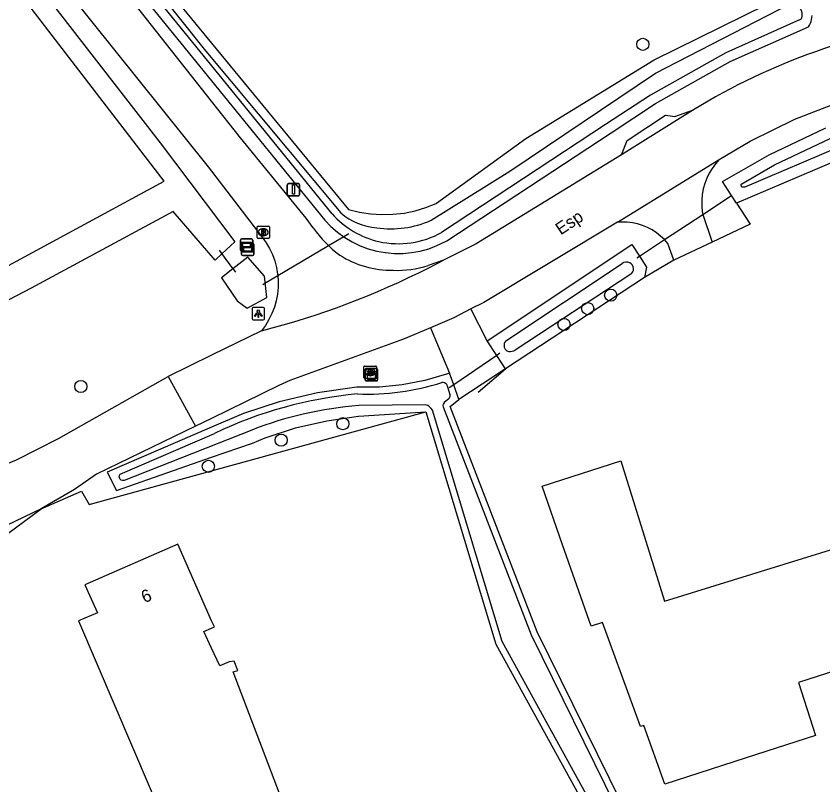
# Model space of a CAD drawing. Extents: x 161389 to 162585, y 388479 to 389761.
# Drawn here: x 162484.3 to 162549.2, y 389564.4 to 389626.2 of the extents above; entities that cross this region are included whole.
import ezdxf

# ---------------------------------------------------------------- set-up
doc = ezdxf.new("R2010")
doc.units = 0
for name, color, linetype in [('IMGEO_Boom', 7, 'Continuous'), ('IMGEO_Bouwland', 7, 'Continuous'), ('IMGEO_Brandkraan', 7, 'Continuous'), ('IMGEO_Duiker', 7, 'Continuous'), ('IMGEO_Erf', 7, 'Continuous'), ('IMGEO_Groenvoorziening', 7, 'Continuous'), ('IMGEO_Hek', 7, 'Continuous'), ('IMGEO_Kast', 7, 'Continuous'), ('IMGEO_Lichtpunt', 7, 'Continuous'), ('IMGEO_Openbare_ruimte_label', 7, 'Continuous'), ('IMGEO_Pand', 7, 'Continuous'), ('IMGEO_Pand_nummerreeks', 7, 'Continuous'), ('IMGEO_Rijbaan_lokaal_gesloten', 7, 'Continuous'), ('IMGEO_Rijbaan_lokaal_open', 7, 'Continuous'), ('IMGEO_Rioolput', 7, 'Continuous'), ('IMGEO_Verkeersbordpaal', 7, 'Continuous'), ('IMGEO_Verklikker', 7, 'Continuous'), ('IMGEO_Voetpad_open', 7, 'Continuous'), ('IMGEO_Waterloop', 7, 'Continuous')]:
    doc.layers.add(name, color=color, linetype=linetype)

msp = doc.modelspace()

# ---------------------------------------------------------------- linework, layer by layer
at = {"layer": 'IMGEO_Boom'}
for centre in [(162534.679, 389623.918), (162532.091, 389603.754), (162530.243, 389602.666), (162528.339, 389601.388), (162489.483, 389596.41), (162510.55, 389593.41), (162505.592, 389592.083), (162499.737, 389589.986)]:
    msp.add_circle(centre, 0.489, dxfattribs=at)
at = {"layer": 'IMGEO_Bouwland'}
msp.add_lwpolyline([(162444.281, 389695.626), (162444.976, 389694.347), (162446.876, 389691.104), (162455.38, 389679.171), (162459.144, 389674.721), (162460.547, 389672.643), (162488.264, 389637.946), (162489.578, 389636.693), (162500, 389624.024), (162511.007, 389610.643), (162511.882, 389610.425), (162512.773, 389610.287), (162513.673, 389610.228), (162514.574, 389610.25), (162515.47, 389610.353), (162516.353, 389610.535), (162517.216, 389610.795), (162518.053, 389611.132), (162518.071, 389611.14), (162525.26, 389616.35), (162535.579, 389622.671), (162546.422, 389628.045)], dxfattribs=at)
at = {"layer": 'IMGEO_Brandkraan'}
for p, q in [((162503.653, 389608.378), (162503.653, 389609.23)), ((162503.728, 389609.304), (162504.58, 389609.304)), ((162504.141, 389609.084), (162504.166, 389609.084)), ((162504.654, 389609.23), (162504.654, 389608.378)), ((162504.164, 389608.524), (162504.139, 389608.524)), ((162504.58, 389608.304), (162503.728, 389608.304))]:
    msp.add_line(p, q, dxfattribs=at)
for points in [[(162503.653, 389608.378), (162503.653, 389609.23)], [(162503.728, 389609.304), (162504.58, 389609.304)], [(162504.001, 389609.004), (162504.001, 389608.604), (162504.214, 389608.604)], [(162504.232, 389609.004), (162504.001, 389609.004)], [(162504.654, 389609.23), (162504.654, 389608.378)], [(162504.18, 389608.923), (162504.126, 389608.923), (162504.126, 389608.847)], [(162504.126, 389608.847), (162504.179, 389608.847)], [(162504.188, 389608.771), (162504.126, 389608.771), (162504.126, 389608.69)], [(162504.126, 389608.69), (162504.188, 389608.69)], [(162504.58, 389608.304), (162503.728, 389608.304)]]:
    msp.add_lwpolyline(points, dxfattribs=at)
for centre, radius, start, end in [((162503.73, 389609.228), 0.0765, 91.55205, 178.44795), ((162503.73, 389609.228), 0.0765, 91.55205, 178.44795), ((162504.236, 389608.859), 0.145, 59.4692, 91.53667), ((162504.261, 389608.906), 0.0922, 285.51372, 58.15012), ((162504.578, 389609.228), 0.0765, 1.55205, 88.44795), ((162504.578, 389609.228), 0.0765, 1.55205, 88.44795), ((162503.73, 389608.38), 0.0765, 181.55205, 268.44795), ((162503.73, 389608.38), 0.0765, 181.55205, 268.44795), ((162504.181, 389608.885), 0.0379, 267.82845, 90.93552), ((162504.189, 389608.73), 0.0404, 269.87594, 90.50774), ((162504.22, 389608.855), 0.251, 268.66757, 293.53466), ((162504.266, 389608.714), 0.105, 301.31148, 78.98903), ((162504.578, 389608.38), 0.0765, 271.55205, 358.44795), ((162504.578, 389608.38), 0.0765, 271.55205, 358.44795)]:
    msp.add_arc(centre, radius, start, end, dxfattribs=at)
for centre, major_axis, ratio, start_param, end_param in [((162504.14, 389608.804), (-0.387, 0.002), 0.722429, 4.712389, 7.853982), ((162504.165, 389608.804), (-0.39, 0.002), 0.717154, 1.570796, 4.712389)]:
    msp.add_ellipse(centre, major_axis=major_axis, ratio=ratio, start_param=start_param, end_param=end_param, dxfattribs=at)
at = {"layer": 'IMGEO_Duiker'}
for points in [[(162534.192, 389606.753), (162534.396, 389606.887), (162536.419, 389608.216), (162539.494, 389610.236), (162541.814, 389611.76)], [(162511.026, 389608.69), (162510.617, 389608.447), (162509.979, 389608.067), (162505.315, 389605.29), (162504.421, 389604.757), (162504.116, 389604.576)], [(162500.595, 389607.36), (162501.146, 389606.618), (162501.201, 389606.543), (162501.223, 389606.514), (162501.485, 389606.161), (162501.499, 389606.143), (162501.554, 389606.068), (162501.647, 389605.943), (162501.907, 389605.593)], [(162523.177, 389599.072), (162522.929, 389598.903), (162519.465, 389596.546), (162519.088, 389596.289)]]:
    msp.add_lwpolyline(points, dxfattribs=at)
at = {"layer": 'IMGEO_Erf'}
for points in [[(162556.26, 389616.875), (162551.015, 389614.89), (162542.21, 389611.153)], [(162534.818, 389605.175), (162523.628, 389597.829)], [(162541.072, 389550.047), (162538.326, 389554.399), (162532.952, 389562.914), (162526.187, 389576.665), (162519.175, 389594.805), (162519.885, 389595.351)], [(162517.235, 389594.37), (162522.858, 389575.675), (162530.551, 389561.722), (162536.666, 389552.847), (162539.23, 389549.09), (162539.513, 389548.715), (162540.796, 389547.168)]]:
    msp.add_lwpolyline(points, dxfattribs=at)
at = {"layer": 'IMGEO_Groenvoorziening'}
for points in [[(162488.254, 389635.427), (162500, 389620.974), (162509.104, 389609.771), (162509.593, 389609.263), (162510.125, 389608.801), (162510.617, 389608.447), (162510.697, 389608.389), (162511.302, 389608.029), (162511.938, 389607.725), (162512.598, 389607.479), (162513.278, 389607.292), (162513.972, 389607.167), (162514.674, 389607.105), (162515.379, 389607.106), (162516.08, 389607.169), (162516.774, 389607.295), (162517.453, 389607.483), (162518.113, 389607.73), (162518.748, 389608.035), (162518.902, 389608.12), (162532.116, 389616.803), (162535.697, 389619.162), (162541.71, 389622.525), (162548, 389625.337), (162548.079, 389625.472), (162548.146, 389625.614), (162548.2, 389625.762), (162548.24, 389625.913), (162548.267, 389626.068), (162548.28, 389626.224)], [(162532.951, 389615.044), (162533.406, 389616.19), (162536.498, 389618.212), (162537.25, 389618.115), (162538.761, 389618.657)], [(162542.21, 389611.153), (162541.814, 389611.76), (162541.087, 389612.876), (162544.825, 389615.043), (162549.393, 389617.208)], [(162542.21, 389611.153), (162543.318, 389609.455), (162540.263, 389608.011)], [(162522.166, 389600.076), (162533.794, 389607.812), (162534.396, 389606.887), (162534.974, 389605.997), (162534.818, 389605.175)], [(162537.178, 389606.553), (162534.818, 389605.175)], [(162519.138, 389597.477), (162518.891, 389597.393), (162517.131, 389596.889), (162515.332, 389596.545), (162513.51, 389596.363), (162511.679, 389596.344), (162508.524, 389595.901), (162505.421, 389595.177), (162502.557, 389594.24), (162500, 389593.133), (162491.61, 389589.502), (162492.351, 389588.053), (162500, 389590.716), (162503.274, 389591.856), (162504.295, 389592.265), (162506.749, 389593.071), (162509.264, 389593.654), (162511.822, 389594.01), (162517.235, 389594.37)], [(162486.294, 389586.559), (162489.546, 389587.986), (162490.14, 389586.904), (162517.235, 389594.37)], [(162469.453, 389581.059), (162480.039, 389582.45), (162482.871, 389584.036), (162486.294, 389586.559)]]:
    msp.add_lwpolyline(points, dxfattribs=at)
at = {"layer": 'IMGEO_Hek'}
msp.add_lwpolyline([(162521.445, 389595.94), (162523.628, 389597.829)], dxfattribs=at)
at = {"layer": 'IMGEO_Kast'}
for p, q in [((162512.344, 389596.928), (162512.344, 389597.769)), ((162512.344, 389597.769), (162512.344, 389596.928)), ((162512.419, 389597.853), (162513.26, 389597.853)), ((162513.26, 389597.853), (162512.419, 389597.853)), ((162513.344, 389597.778), (162513.344, 389596.937)), ((162513.344, 389596.937), (162513.344, 389597.778)), ((162513.269, 389596.853), (162512.428, 389596.853)), ((162512.428, 389596.853), (162513.269, 389596.853))]:
    msp.add_line(p, q, dxfattribs=at)
for points in [[(162512.539, 389597.643), (162513.139, 389597.643), (162513.139, 389597.558), (162512.539, 389597.558), (162512.539, 389597.643)], [(162512.539, 389597.468), (162513.139, 389597.468), (162513.139, 389596.979), (162512.539, 389596.979), (162512.539, 389597.468)]]:
    msp.add_lwpolyline(points, dxfattribs=at)
msp.add_circle((162512.623, 389597.317), 0.0377, dxfattribs=at)
for centre, start, end in [((162512.422, 389597.775), 92.4484, 184.28452), ((162512.422, 389597.775), 92.4484, 184.28452), ((162513.266, 389597.775), 2.4484, 94.28452), ((162513.266, 389597.775), 2.4484, 94.28452), ((162512.422, 389596.931), 182.4484, 274.28452), ((162512.422, 389596.931), 182.4484, 274.28452), ((162513.266, 389596.931), 272.4484, 4.28452), ((162513.266, 389596.931), 272.4484, 4.28452)]:
    msp.add_arc(centre, 0.0779, start, end, dxfattribs=at)
at = {"layer": 'IMGEO_Lichtpunt'}
for p, q in [((162503.253, 389602.663), (162503.253, 389601.856)), ((162503.253, 389602.663), (162503.253, 389601.856)), ((162504.155, 389602.758), (162503.347, 389602.758)), ((162504.155, 389602.758), (162503.347, 389602.758)), ((162504.249, 389601.856), (162504.249, 389602.663)), ((162504.249, 389601.856), (162504.249, 389602.663)), ((162503.347, 389601.762), (162504.155, 389601.762)), ((162503.347, 389601.762), (162504.155, 389601.762))]:
    msp.add_line(p, q, dxfattribs=at)
for points in [[(162503.627, 389602.327), (162503.666, 389602.299), (162503.478, 389602.037), (162503.44, 389602.064), (162503.627, 389602.327)], [(162503.729, 389602.279), (162503.776, 389602.279), (162503.776, 389601.957), (162503.729, 389601.957), (162503.729, 389602.279)], [(162503.839, 389602.299), (162503.877, 389602.326), (162504.064, 389602.064), (162504.025, 389602.036), (162503.839, 389602.299)]]:
    msp.add_lwpolyline(points, dxfattribs=at)
msp.add_circle((162503.752, 389602.461), 0.0994, dxfattribs=at)
for centre, start, end in [((162503.347, 389602.663), 90, 180), ((162503.347, 389602.663), 90, 180), ((162504.155, 389602.663), 0, 90), ((162504.155, 389602.663), 0, 90), ((162503.347, 389601.856), 180, 270), ((162503.347, 389601.856), 180, 270), ((162504.155, 389601.856), 270, 0), ((162504.155, 389601.856), 270, 360)]:
    msp.add_arc(centre, 0.0946, start, end, dxfattribs=at)
at = {"layer": 'IMGEO_Pand'}
for points in [[(162565.517, 389578.496), (162547.191, 389572.588), (162548.561, 389568.331), (162543.802, 389566.8), (162536.446, 389564.434), (162534.742, 389569.151), (162534.484, 389569.057), (162531.437, 389577.419), (162530.514, 389577.136), (162528.223, 389583.678), (162526.571, 389588.397), (162532.896, 389590.432), (162536.408, 389579.136), (162562.687, 389587.272), (162565.517, 389578.496)], [(162499.328, 389554.103), (162500, 389554.371), (162507.803, 389557.479), (162501.735, 389573.462), (162502.112, 389573.572), (162501.817, 389574.322), (162501.417, 389574.255), (162500.655, 389573.945), (162500, 389575.362), (162499.378, 389576.707), (162500, 389576.982), (162500.217, 389577.078), (162500, 389577.568), (162497.277, 389583.713), (162489.806, 389580.447), (162490.812, 389578.214), (162489.287, 389577.554), (162499.328, 389554.103)]]:
    msp.add_lwpolyline(points, dxfattribs=at)
at = {"layer": 'IMGEO_Rijbaan_lokaal_gesloten'}
for points in [[(162508.175, 389609.158), (162507.599, 389609.947), (162502.332, 389616.392), (162500, 389619.349), (162487.536, 389635.155), (162471.962, 389655.135), (162460.381, 389668.927)], [(162457.368, 389666.342), (162468.15, 389652.663), (162484.593, 389632.945), (162499.723, 389614.076), (162500, 389613.714), (162504.042, 389608.438), (162504.066, 389608.408), (162504.38, 389607.967), (162504.653, 389607.499), (162504.884, 389607.009), (162505.07, 389606.5), (162505.209, 389605.977), (162505.302, 389605.443), (162505.315, 389605.29), (162505.346, 389604.904), (162505.342, 389604.362), (162505.289, 389603.823), (162505.189, 389603.291), (162505.041, 389602.77), (162504.848, 389602.264), (162504.61, 389601.778), (162504.33, 389601.314), (162504.009, 389600.878)], [(162518.658, 389606.555), (162517.4, 389606.137)], [(162517.458, 389605.949), (162518.658, 389606.555)], [(162409.988, 389580.122), (162414.314, 389582.066), (162419.315, 389583.822), (162424.453, 389585.125), (162429.686, 389585.963), (162434.974, 389586.33), (162436.417, 389586.413), (162439.61, 389586.598), (162464.371, 389586.252), (162468.477, 389586.379), (162472.556, 389586.873), (162476.574, 389587.729), (162480.499, 389588.94), (162484.301, 389590.498), (162487.678, 389592.234), (162496.502, 389597.202)], [(162496.502, 389597.202), (162498.712, 389593.205)], [(162498.712, 389593.205), (162490.738, 389589.364), (162488.966, 389588.132), (162486.294, 389586.559)], [(162486.294, 389586.559), (162483.492, 389585.232), (162480.582, 389584.16), (162477.589, 389583.352), (162474.535, 389582.815), (162466.407, 389582.224), (162437.665, 389582.372), (162436.345, 389582.328), (162428.651, 389581.666), (162425.623, 389581.213), (162425.125, 389580.99)]]:
    msp.add_lwpolyline(points, dxfattribs=at)
for centre, radius, start, end in [((162515.884, 389614.512), 9.386, 214.78193, 233.49202), ((162514.493, 389613.551), 7.805, 237.50831, 270.7595), ((162487.359, 389665.406), 66.642, 284.46834, 296.84997), ((162514.92, 389613.691), 7.95, 267.66256, 288.17404)]:
    msp.add_arc(centre, radius, start, end, dxfattribs=at)
at = {"layer": 'IMGEO_Rijbaan_lokaal_open'}
for points in [[(162540.808, 389614.65), (162543.297, 389616.119), (162546.908, 389617.892), (162550.663, 389619.336), (162554.532, 389620.438), (162557.552, 389621.024), (162561.524, 389621.473), (162562.854, 389621.493)], [(162538.761, 389618.657), (162532.951, 389615.044)], [(162532.951, 389615.044), (162521.27, 389607.875), (162518.658, 389606.555)], [(162532.625, 389609.608), (162540.808, 389614.65)], [(162540.808, 389614.65), (162540.511, 389614.309), (162540.245, 389613.942), (162540.013, 389613.553), (162539.817, 389613.146), (162539.658, 389612.722), (162539.537, 389612.285), (162539.456, 389611.84), (162539.415, 389611.389), (162539.414, 389610.936), (162539.454, 389610.485), (162539.494, 389610.236), (162540.263, 389608.011)], [(162532.625, 389609.608), (162521.889, 389603.165), (162520.856, 389602.637)], [(162537.178, 389606.553), (162536.693, 389607.913), (162536.419, 389608.216), (162536.108, 389608.504), (162535.774, 389608.763), (162535.417, 389608.991), (162535.041, 389609.186), (162534.649, 389609.347), (162534.245, 389609.473), (162533.831, 389609.561), (162533.41, 389609.613), (162532.987, 389609.626), (162532.625, 389609.608)], [(162540.263, 389608.011), (162537.178, 389606.553)], [(162520.856, 389602.637), (162519.486, 389601.936), (162517.589, 389601.132)], [(162504.009, 389600.878), (162500, 389598.915), (162496.502, 389597.202)], [(162517.589, 389601.132), (162515.441, 389600.222), (162506.297, 389596.882), (162505.406, 389596.487), (162500, 389593.836), (162498.712, 389593.205)]]:
    msp.add_lwpolyline(points, dxfattribs=at)
msp.add_arc((162565.779, 389574.575), 51.702, 97.41083, 121.50429, dxfattribs=at)
at = {"layer": 'IMGEO_Rioolput'}
for p, q in [((162512.251, 389597.124), (162512.251, 389597.976)), ((162512.326, 389598.05), (162513.178, 389598.05)), ((162513.252, 389597.976), (162513.252, 389597.124)), ((162512.739, 389597.83), (162512.764, 389597.83)), ((162513.178, 389597.05), (162512.326, 389597.05)), ((162512.762, 389597.27), (162512.737, 389597.27))]:
    msp.add_line(p, q, dxfattribs=at)
for points in [[(162512.251, 389597.124), (162512.251, 389597.976)], [(162512.326, 389598.05), (162513.178, 389598.05)], [(162513.252, 389597.976), (162513.252, 389597.124)], [(162512.84, 389597.748), (162512.588, 389597.75), (162512.588, 389597.35)], [(162512.588, 389597.35), (162512.712, 389597.35), (162512.712, 389597.512), (162512.723, 389597.512)], [(162512.766, 389597.669), (162512.712, 389597.669), (162512.712, 389597.588)], [(162512.712, 389597.588), (162512.764, 389597.588)], [(162512.77, 389597.483), (162512.841, 389597.35), (162512.981, 389597.35), (162512.916, 389597.476)], [(162513.178, 389597.05), (162512.326, 389597.05)]]:
    msp.add_lwpolyline(points, dxfattribs=at)
for centre, radius, start, end in [((162512.328, 389597.974), 0.0765, 91.55205, 178.44795), ((162512.328, 389597.974), 0.0765, 91.55205, 178.44795), ((162513.176, 389597.974), 0.0765, 1.55205, 88.44795), ((162513.176, 389597.974), 0.0765, 1.55205, 88.44795), ((162512.722, 389597.459), 0.0533, 26.02933, 88.69889), ((162512.748, 389597.777), 0.19, 274.7715, 282.96867), ((162512.772, 389597.573), 0.0964, 77.00612, 93.18647), ((162512.786, 389597.63), 0.0378, 276.66336, 79.67722), ((162512.839, 389597.638), 0.109, 350.36119, 89.41601), ((162512.837, 389597.638), 0.112, 277.58423, 350.98172), ((162512.821, 389597.423), 0.108, 29.51342, 73.79051), ((162512.328, 389597.126), 0.0765, 181.55205, 268.44795), ((162512.328, 389597.126), 0.0765, 181.55205, 268.44795), ((162513.176, 389597.126), 0.0765, 271.55205, 358.44795), ((162513.176, 389597.126), 0.0765, 271.55205, 358.44795)]:
    msp.add_arc(centre, radius, start, end, dxfattribs=at)
for centre, major_axis, ratio, start_param, end_param in [((162512.738, 389597.55), (-0.387, 0.002), 0.722429, 4.712389, 7.853982), ((162512.763, 389597.55), (-0.39, 0.002), 0.717154, 1.570796, 4.712389)]:
    msp.add_ellipse(centre, major_axis=major_axis, ratio=ratio, start_param=start_param, end_param=end_param, dxfattribs=at)
at = {"layer": 'IMGEO_Verkeersbordpaal'}
for p, q in [((162506.086, 389611.833), (162506.086, 389612.633)), ((162506.086, 389612.633), (162506.086, 389611.833)), ((162506.186, 389612.733), (162506.976, 389612.733)), ((162506.976, 389612.733), (162506.186, 389612.733)), ((162507.076, 389612.633), (162507.076, 389611.833)), ((162507.076, 389611.833), (162507.076, 389612.633)), ((162506.976, 389611.733), (162506.186, 389611.733)), ((162506.186, 389611.733), (162506.976, 389611.733))]:
    msp.add_line(p, q, dxfattribs=at)
msp.add_lwpolyline([(162506.506, 389612.608), (162506.656, 389612.608), (162506.656, 389611.858), (162506.506, 389611.858), (162506.506, 389612.608)], dxfattribs=at)
for centre, start, end in [((162506.186, 389612.633), 90, 180), ((162506.186, 389612.633), 90, 180), ((162506.976, 389612.633), 0, 90), ((162506.976, 389612.633), 360, 90), ((162506.186, 389611.833), 180, 270), ((162506.186, 389611.833), 180, 270), ((162506.976, 389611.833), 270, 0), ((162506.976, 389611.833), 270, 0)]:
    msp.add_arc(centre, 0.1, start, end, dxfattribs=at)
at = {"layer": 'IMGEO_Verklikker'}
for p, q in [((162502.309, 389607.376), (162502.309, 389608.176)), ((162502.309, 389608.176), (162502.309, 389607.376)), ((162502.401, 389607.024), (162502.401, 389607.824)), ((162502.401, 389607.824), (162502.401, 389607.024)), ((162502.409, 389608.276), (162503.199, 389608.276)), ((162503.199, 389608.276), (162502.409, 389608.276)), ((162502.501, 389607.924), (162503.291, 389607.924)), ((162503.291, 389607.924), (162502.501, 389607.924)), ((162503.299, 389608.176), (162503.299, 389607.376)), ((162503.299, 389607.376), (162503.299, 389608.176)), ((162503.391, 389607.824), (162503.391, 389607.024)), ((162503.391, 389607.024), (162503.391, 389607.824)), ((162503.199, 389607.276), (162502.409, 389607.276)), ((162502.409, 389607.276), (162503.199, 389607.276)), ((162503.291, 389606.924), (162502.501, 389606.924)), ((162502.501, 389606.924), (162503.291, 389606.924))]:
    msp.add_line(p, q, dxfattribs=at)
for points in [[(162502.41, 389608.008), (162503.198, 389608.008), (162503.198, 389607.544), (162502.41, 389607.544), (162502.41, 389608.008)], [(162502.475, 389607.943), (162502.475, 389607.609), (162503.133, 389607.609), (162503.133, 389607.943), (162502.475, 389607.943)], [(162502.502, 389607.656), (162503.29, 389607.656), (162503.29, 389607.192), (162502.502, 389607.192), (162502.502, 389607.656)], [(162502.567, 389607.591), (162502.567, 389607.257), (162503.225, 389607.257), (162503.225, 389607.591), (162502.567, 389607.591)]]:
    msp.add_lwpolyline(points, dxfattribs=at)
for centre, start, end in [((162502.409, 389608.176), 90, 180), ((162502.409, 389608.176), 90, 180), ((162502.501, 389607.824), 90, 180), ((162502.501, 389607.824), 90, 180), ((162503.199, 389608.176), 0, 90), ((162503.199, 389608.176), 360, 90), ((162503.291, 389607.824), 0, 90), ((162503.291, 389607.824), 360, 90), ((162502.409, 389607.376), 180, 270), ((162502.409, 389607.376), 180, 270), ((162503.199, 389607.376), 270, 0), ((162503.199, 389607.376), 270, 0), ((162502.501, 389607.024), 180, 270), ((162502.501, 389607.024), 180, 270), ((162503.291, 389607.024), 270, 0), ((162503.291, 389607.024), 270, 0)]:
    msp.add_arc(centre, 0.1, start, end, dxfattribs=at)
at = {"layer": 'IMGEO_Voetpad_open'}
for points in [[(162522.166, 389600.076), (162520.856, 389602.637)], [(162517.589, 389601.132), (162519.138, 389597.477)], [(162523.628, 389597.829), (162522.929, 389598.903), (162522.166, 389600.076)], [(162519.885, 389595.351), (162519.465, 389596.546), (162519.138, 389597.477)], [(162523.628, 389597.829), (162519.885, 389595.351)]]:
    msp.add_lwpolyline(points, dxfattribs=at)
at = {"layer": 'IMGEO_Waterloop'}
for points in [[(162480.118, 389604.237), (162496.188, 389612.908), (162481.084, 389632.533), (162456.218, 389661.773), (162455.163, 389662.824), (162449.463, 389669.131), (162445.046, 389674.921), (162440.477, 389682.073), (162436.565, 389689.605)], [(162459.319, 389673.752), (162499.393, 389623.525), (162510.388, 389610.356)], [(162457.733, 389662.99), (162482.436, 389633.29), (162495.856, 389615.998), (162501.859, 389608.049), (162500.817, 389607.061), (162500.283, 389606.554), (162496.893, 389610.475), (162485.48, 389604.317), (162481.249, 389602.123)], [(162509.693, 389610.292), (162500.61, 389621.47), (162488.867, 389635.919)], [(162517.644, 389609.766), (162523.986, 389613.721), (162535.683, 389621.595), (162546.472, 389627.155)], [(162547.281, 389625.877), (162541.357, 389623.228), (162535.288, 389619.834), (162531.684, 389617.46), (162518.496, 389608.794)], [(162542.564, 389612.602), (162542.645, 389612.71), (162545.256, 389614.223), (162549.752, 389616.354), (162554.44, 389618.082)], [(162556.132, 389617.816), (162550.67, 389615.749), (162542.877, 389612.441)], [(162542.877, 389612.441), (162542.728, 389612.427), (162542.706, 389612.43), (162542.664, 389612.439)], [(162500.799, 389605.13), (162502.062, 389603.302), (162502.856, 389602.704), (162504.443, 389603.561), (162504.244, 389605.272), (162502.899, 389606.807), (162501.71, 389605.858), (162500.799, 389605.13)], [(162523.652, 389600.073), (162533.01, 389606.298)], [(162533.699, 389605.428), (162524.413, 389599.333)], [(162523.636, 389599.37), (162523.531, 389599.597)], [(162518.876, 389596.584), (162518.953, 389596.366), (162519.164, 389595.763)], [(162519.132, 389595.515), (162519.061, 389595.402), (162518.729, 389595.147)], [(162517.207, 389594.936), (162511.831, 389594.872)], [(162518.606, 389594.771), (162525.689, 389576.447), (162532.477, 389562.648), (162537.867, 389554.109), (162540.628, 389549.734), (162543.969, 389545.48), (162547.044, 389540.999), (162549.281, 389536.684), (162551.339, 389531.009), (162553.057, 389526.283)], [(162553.023, 389524.065), (162552.828, 389524.145), (162552.749, 389524.207), (162552.626, 389524.387), (162552.561, 389524.538), (162552.495, 389524.762), (162552.373, 389525.281), (162550.517, 389532.219), (162548.715, 389536.979), (162547.511, 389539.233), (162544.866, 389543.113), (162541.214, 389547.515), (162539.939, 389549.052), (162539.671, 389549.407), (162537.114, 389553.154), (162531.013, 389562.008), (162523.361, 389575.887), (162517.765, 389594.494)], [(162503.226, 389592.903), (162492.953, 389588.838), (162492.831, 389588.849), (162492.721, 389588.876)], [(162492.571, 389589.12), (162492.601, 389589.257), (162492.649, 389589.36), (162500.216, 389592.635)]]:
    msp.add_lwpolyline(points, dxfattribs=at)
for centre, radius, start, end in [((162546.52, 389626.288), 0.975, 352.92641, 61.55615), ((162547.138, 389626.196), 0.35, 294.06216, 355.34819), ((162542.701, 389612.574), 0.14, 168.38864, 254.66934), ((162515.029, 389614.995), 7.113, 221.38854, 257.18737), ((162513.65, 389614.195), 5.037, 229.64508, 265.77818), ((162514.431, 389617.027), 7.94, 261.65708, 293.8674), ((162515.018, 389614.989), 7.105, 257.26971, 299.3116), ((162533.368, 389605.737), 0.665, 66.42471, 122.55524), ((162533.326, 389605.832), 0.6, 5.82675, 59.13197), ((162533.37, 389605.873), 0.553, 306.48564, 2.07223), ((162524.006, 389599.73), 0.493, 135.86069, 195.61412), ((162523.987, 389599.678), 0.467, 221.27147, 259.37857), ((162523.974, 389600.097), 0.881, 265.22602, 299.87899), ((162512.441, 389616.046), 20.258, 267.96159, 287.45513), ((162518.591, 389596.376), 0.353, 36.11191, 102.11282), ((162514.844, 389561.968), 33.977, 95.27472, 115.5), ((162518.87, 389595.675), 0.307, 328.6042, 16.69104), ((162514.167, 389564.875), 30.088, 94.45309, 111.32403), ((162516.864, 389593.929), 1.064, 32.07076, 71.16272), ((162518.998, 389594.851), 0.4, 132.25728, 191.51402), ((162492.835, 389589.114), 0.264, 178.79752, 244.36507)]:
    msp.add_arc(centre, radius, start, end, dxfattribs=at)

# ---------------------------------------------------------------- texts
at = {"layer": 'IMGEO_Openbare_ruimte_label'}
msp.add_text('Esp', height=1, rotation=33.62653, dxfattribs=at).set_placement((162528.07, 389608.543))
at = {"layer": 'IMGEO_Pand_nummerreeks'}
msp.add_text('6', height=1, rotation=23.61288, dxfattribs=at).set_placement((162494.603, 389578.965))

doc.saveas('drawing.dxf')
